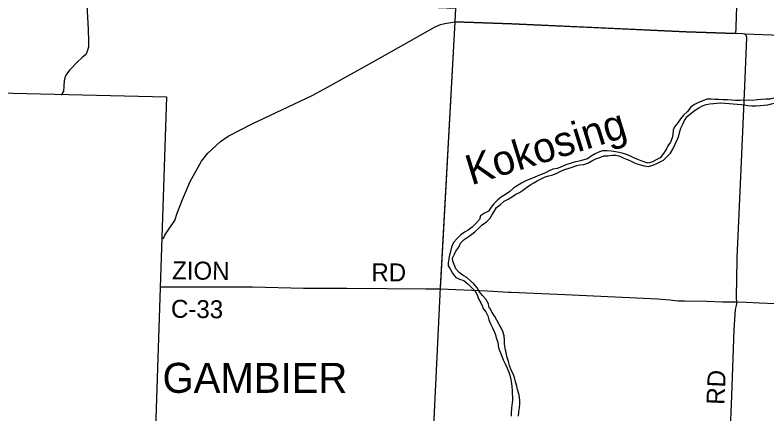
# Model space of a CAD drawing. Extents: x 41.3 to 81.6, y -19.3 to 2.7.
# Drawn here: x 46.925 to 48.932, y -0.064 to 1 of the extents above; entities that cross this region are included whole.
import ezdxf

# ---------------------------------------------------------------- set-up
doc = ezdxf.new("R2010")
doc.units = 0
for name, color, linetype in [('GM_X_Corporation', 7, 'Continuous'), ('GM_X_Corporation_Text', 7, 'Continuous'), ('GM_X_County_Road', 7, 'Continuous'), ('GM_X_County_Road_Text', 7, 'Continuous'), ('GM_X_Major_River', 7, 'Continuous'), ('GM_X_Major_River_Text', 7, 'Continuous'), ('GM_X_Township', 7, 'Continuous'), ('GM_X_Township_Road', 7, 'Continuous')]:
    doc.layers.add(name, color=color, linetype=linetype)

msp = doc.modelspace()

# ---------------------------------------------------------------- linework, layer by layer
at = {"layer": 'GM_X_Corporation'}
msp.add_lwpolyline([(46.584, 0.4876), (46.608, 0.4783), (46.619, 0.799), (47.3288, 0.7822), (47.2918, -0.3441), (47.053, -0.3369), (47.053, -0.2918), (46.8252, -0.1011), (46.7581, -0.0438), (46.7215, -0.0005), (46.7256, 0.0209), (46.722, 0.0646), (46.7171, 0.1029), (46.7053, 0.1736), (46.6837, 0.2398), (46.6465, 0.2782), (46.6014, 0.293), (46.6062, 0.436), (46.6004, 0.4311), (46.5985, 0.4242), (46.5815, 0.4287), (46.5709, 0.4515)], close=True, dxfattribs=at)
at = {"layer": 'GM_X_County_Road'}
for points in [[(48.8494, 0.9506), (48.85, 0.9656), (48.8511, 0.999), (48.8585, 1.1918), (48.8618, 1.2505)], [(48.8743, 0.948), (48.8731, 0.9493), (48.8673, 0.9496), (48.8494, 0.9506)], [(48.8515, 0.235), (48.8507, 0.2444), (48.8508, 0.2529), (48.8518, 0.293), (48.8528, 0.3519), (48.8637, 0.589), (48.8731, 0.8099), (48.8781, 0.9398), (48.8765, 0.9454), (48.8743, 0.948)], [(47.3125, 0.2753), (47.4287, 0.2748)], [(47.4287, 0.2748), (47.4359, 0.2748), (47.559, 0.2749), (47.6946, 0.2717), (47.8045, 0.2712), (47.8105, 0.2712)], [(47.8105, 0.2712), (47.9185, 0.2707), (48.0214, 0.2699), (48.0264, 0.2698)], [(48.0264, 0.2698), (48.0273, 0.2698), (48.0596, 0.2698)], [(48.0596, 0.2698), (48.0596, 0.2698), (48.1859, 0.264), (48.2417, 0.2609), (48.2489, 0.2606)], [(48.2489, 0.2606), (48.3925, 0.2544), (48.5651, 0.2463), (48.6401, 0.243), (48.6731, 0.2402), (48.6951, 0.238), (48.7121, 0.2376), (48.7719, 0.2371), (48.8135, 0.2353), (48.8515, 0.235), (48.8772, 0.2338), (48.9123, 0.2322), (48.9956, 0.2288)], [(48.8102, -0.7486), (48.813, -0.6703), (48.823, -0.4156), (48.8336, -0.1239), (48.8383, -0.0159), (48.8447, 0.1605), (48.8484, 0.2147), (48.8509, 0.225), (48.8521, 0.23), (48.8515, 0.235)]]:
    msp.add_lwpolyline(points, dxfattribs=at)
at = {"layer": 'GM_X_Major_River'}
for points in [[(48.8813, 0.7591), (48.8919, 0.7579), (48.9031, 0.7577), (48.9136, 0.7588), (48.9248, 0.7595), (48.9347, 0.7606), (48.9446, 0.7629), (48.9558, 0.7656), (48.9673, 0.7686), (48.9782, 0.7713), (48.9884, 0.7746), (48.9996, 0.7782), (49.0094, 0.7822), (49.02, 0.7858)], [(48.9637, 0.7833), (48.9531, 0.7794), (48.941, 0.776), (48.9288, 0.7756), (48.9176, 0.7745), (48.9058, 0.7734), (48.8946, 0.7723)], [(48.8946, 0.7723), (48.8834, 0.7726), (48.8603, 0.7723), (48.8482, 0.7719), (48.8373, 0.7727), (48.8264, 0.7739), (48.8149, 0.7741), (48.804, 0.7743), (48.7931, 0.7748), (48.7831, 0.776), (48.7716, 0.7756), (48.7605, 0.771), (48.7496, 0.7664), (48.7385, 0.7617), (48.7286, 0.754), (48.7198, 0.743), (48.7096, 0.7329), (48.7017, 0.7229), (48.6941, 0.7122), (48.6856, 0.7019), (48.6819, 0.6926), (48.6804, 0.6816), (48.6792, 0.672), (48.6742, 0.6607), (48.6679, 0.651), (48.6635, 0.643), (48.6562, 0.6307), (48.6471, 0.6191), (48.6359, 0.6135), (48.6248, 0.6073), (48.6146, 0.6046), (48.6065, 0.6071), (48.5959, 0.6109), (48.5876, 0.6143), (48.5763, 0.6193), (48.566, 0.624), (48.5544, 0.629), (48.5458, 0.6318), (48.5371, 0.6337), (48.5281, 0.6352), (48.5169, 0.6367), (48.5054, 0.6375), (48.4932, 0.6374), (48.4849, 0.6354), (48.4734, 0.6301), (48.4626, 0.6236), (48.4531, 0.6168), (48.4429, 0.6138), (48.4342, 0.6114), (48.4259, 0.6091), (48.4176, 0.6071), (48.4065, 0.6038), (48.395, 0.6001), (48.3832, 0.5952), (48.3717, 0.5909), (48.3608, 0.5886), (48.3509, 0.5846), (48.3427, 0.5797), (48.3318, 0.5751), (48.3203, 0.5715), (48.3102, 0.5662), (48.299, 0.5623), (48.2881, 0.5577), (48.277, 0.5511), (48.2566, 0.5387), (48.2458, 0.5296), (48.2341, 0.5215), (48.2236, 0.515), (48.2131, 0.5065), (48.2026, 0.4968), (48.1957, 0.4871), (48.1884, 0.4771), (48.1779, 0.4719), (48.1671, 0.4647), (48.1643, 0.4547), (48.1552, 0.4441), (48.1453, 0.434), (48.1345, 0.4262), (48.1243, 0.421), (48.1145, 0.4135), (48.105, 0.4038), (48.0955, 0.3931), (48.0898, 0.3812), (48.0874, 0.3696), (48.0849, 0.3597), (48.0831, 0.35), (48.081, 0.3394), (48.0811, 0.3314), (48.086, 0.3228), (48.0925, 0.3116), (48.1006, 0.3012), (48.1115, 0.2955), (48.1228, 0.2921), (48.1331, 0.2829), (48.1435, 0.2731), (48.1538, 0.2629), (48.1591, 0.2511), (48.1617, 0.2428), (48.1682, 0.2326), (48.1731, 0.2221), (48.1739, 0.2178)], [(48.1921, 0.2178), (48.1908, 0.2194), (48.1887, 0.2299), (48.1819, 0.2417), (48.1728, 0.2522), (48.1641, 0.2624), (48.1588, 0.2723), (48.1494, 0.2834), (48.141, 0.2913), (48.131, 0.2999), (48.121, 0.3052), (48.1101, 0.3128), (48.1016, 0.3233), (48.0971, 0.3345), (48.0934, 0.3434), (48.0924, 0.3514), (48.0977, 0.362), (48.1018, 0.3701), (48.1094, 0.3808), (48.1141, 0.3911), (48.1239, 0.4011), (48.1341, 0.4086), (48.1439, 0.4151), (48.1525, 0.4213), (48.162, 0.431), (48.1718, 0.4404), (48.183, 0.4485), (48.1928, 0.4582), (48.1975, 0.4663), (48.2038, 0.4763), (48.2101, 0.4863), (48.2206, 0.4948), (48.2308, 0.5032), (48.2413, 0.5088), (48.2527, 0.5156), (48.2613, 0.5221), (48.2712, 0.5264), (48.2798, 0.5316), (48.2903, 0.5397), (48.3017, 0.5475), (48.31, 0.5521), (48.3182, 0.5573), (48.3291, 0.5629), (48.3402, 0.5685), (48.3495, 0.5714), (48.3607, 0.5741), (48.3709, 0.5784), (48.382, 0.5836), (48.3916, 0.5879), (48.4018, 0.5909), (48.4123, 0.5945), (48.4241, 0.5982), (48.4324, 0.6002), (48.4436, 0.6016), (48.4538, 0.6052), (48.4647, 0.6114), (48.4755, 0.6164), (48.4863, 0.6197), (48.4969, 0.6246), (48.5077, 0.6247), (48.518, 0.6261), (48.5285, 0.6262), (48.5391, 0.6231), (48.5501, 0.6184), (48.5597, 0.6143), (48.5713, 0.609), (48.5822, 0.604), (48.5941, 0.6003), (48.6041, 0.5975), (48.6147, 0.596), (48.6249, 0.5983), (48.6367, 0.6033), (48.6472, 0.6082), (48.6555, 0.6128), (48.6659, 0.6225), (48.6742, 0.6319), (48.6811, 0.6425), (48.6874, 0.6551), (48.693, 0.6693), (48.6964, 0.678), (48.6998, 0.6892), (48.7023, 0.6982), (48.7073, 0.7085), (48.712, 0.7188), (48.7193, 0.7292), (48.7297, 0.7386), (48.7402, 0.7461), (48.7498, 0.7522), (48.76, 0.7581), (48.7698, 0.7614), (48.7798, 0.7635), (48.7894, 0.7642), (48.7983, 0.7653), (48.8085, 0.7657), (48.8198, 0.7652), (48.8313, 0.764), (48.8416, 0.7631), (48.8528, 0.7623), (48.8637, 0.7614), (48.872, 0.7603), (48.8813, 0.7591)], [(48.1739, 0.2178), (48.1812, 0.2079), (48.1873, 0.1976), (48.1898, 0.1867), (48.1939, 0.1767), (48.1997, 0.1655), (48.2041, 0.1555), (48.2073, 0.1472), (48.2095, 0.1388), (48.2133, 0.1276), (48.2149, 0.1173), (48.2165, 0.1093), (48.2206, 0.0987), (48.2241, 0.0904), (48.2282, 0.0801), (48.233, 0.0692), (48.2384, 0.0579), (48.2429, 0.0473), (48.2454, 0.0393), (48.2479, 0.0281), (48.2498, 0.0175), (48.2511, 0.0094), (48.2523, -0.0015), (48.2523, -0.0095), (48.2529, -0.0201), (48.2529, -0.0284), (48.2513, -0.0403), (48.2503, -0.0499), (48.2493, -0.0614), (48.2493, -0.0701)], [(48.2688, -0.0698), (48.2698, -0.0586), (48.2711, -0.048), (48.2724, -0.0371), (48.2721, -0.0291), (48.2715, -0.0195), (48.2696, -0.0108), (48.2664, 0.0007), (48.2642, 0.0104), (48.2611, 0.0219), (48.2582, 0.0328), (48.2541, 0.0431), (48.249, 0.0531), (48.2449, 0.0653), (48.2423, 0.0759), (48.2388, 0.0861), (48.2369, 0.0942), (48.2347, 0.1038), (48.2331, 0.1118), (48.2316, 0.1221), (48.2316, 0.133), (48.2307, 0.1445), (48.2269, 0.1555), (48.223, 0.1638), (48.217, 0.1747), (48.2106, 0.1857), (48.2058, 0.1959), (48.1985, 0.2069), (48.1921, 0.2178)]]:
    msp.add_lwpolyline(points, dxfattribs=at)
at = {"layer": 'GM_X_Township'}
for points in [[(46.6323, 1.082), (46.9356, 1.0671), (47.0053, 1.0645), (47.0849, 1.0611), (47.1126, 1.0599), (47.341, 1.0494), (47.5073, 1.0425), (48.1003, 1.0179), (48.0986, 0.982), (48.0693, 0.447), (48.0597, 0.2729), (48.0177, -0.5949), (47.9927, -1.1134), (47.3982, -1.085), (46.8967, -1.0581)], [(49.8429, 0.9122), (48.8731, 0.9493), (48.8673, 0.9496), (48.8494, 0.9506), (48.7166, 0.9552), (48.2508, 0.9768), (48.0986, 0.982), (48.0597, 0.2729), (48.0177, -0.5949), (47.9927, -1.1134), (47.9826, -1.3785), (47.9474, -2.0041), (47.9161, -2.7711), (47.8928, -3.2748), (47.902, -3.2801), (47.9094, -3.2815), (47.9235, -3.2831), (48.0099, -3.2846), (48.5864, -3.309), (48.645, -3.3113), (49.6175, -3.339)]]:
    msp.add_lwpolyline(points, dxfattribs=at)
at = {"layer": 'GM_X_Township_Road'}
for points in [[(47.1126, 1.0599), (47.1165, 1.0262), (47.1201, 0.9615), (47.1207, 0.9307), (47.1207, 0.9142), (47.1162, 0.9002), (47.1129, 0.8939), (47.1048, 0.8873), (47.0892, 0.8736), (47.0761, 0.8591), (47.0702, 0.8533), (47.0603, 0.8394), (47.0575, 0.8328), (47.0556, 0.8247), (47.0539, 0.7966), (47.0478, 0.7858)], [(48.1003, 1.0179), (48.0986, 0.982)], [(47.32, 0.4027), (47.3244, 0.4129), (47.3367, 0.4312), (47.3508, 0.4522), (47.3577, 0.4717), (47.3718, 0.5076), (47.3923, 0.5556), (47.4228, 0.6098), (47.4395, 0.6313), (47.4733, 0.6625), (47.4938, 0.6765), (47.5581, 0.7098), (47.7183, 0.7852), (47.751, 0.803), (47.8792, 0.8747), (48.0463, 0.9685), (48.0604, 0.9749), (48.0719, 0.9774), (48.0986, 0.982)], [(48.0986, 0.982), (48.0693, 0.447), (48.0596, 0.2698)], [(48.0986, 0.982), (48.0986, 0.982), (48.2508, 0.9768), (48.4698, 0.9666)], [(48.4698, 0.9666), (48.7166, 0.9552), (48.8494, 0.9506)]]:
    msp.add_lwpolyline(points, dxfattribs=at)

# ---------------------------------------------------------------- texts
at = {"layer": 'GM_X_Corporation_Text'}
msp.add_text('GAMBIER', height=0.08, rotation=0, dxfattribs=at).set_placement((47.3184, -0.0078))
at = {"layer": 'GM_X_County_Road_Text'}
for s, rotation, p in [('ZION', 359.4265, (47.3438, 0.2949)), ('RD', 359.5063, (47.8758, 0.29)), ('C-33', 359.3124, (47.3408, 0.1926)), ('RD', 87.5323, (48.8184, -0.0404))]:
    msp.add_text(s, height=0.048, rotation=rotation, dxfattribs=at).set_placement(p)
at = {"layer": 'GM_X_Major_River_Text'}
msp.add_text('Kokosing', height=0.08001, rotation=17.2306, dxfattribs=at).set_placement((48.1427, 0.5456))

doc.saveas('drawing.dxf')
